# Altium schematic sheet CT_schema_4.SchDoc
size 282 x 169 mm
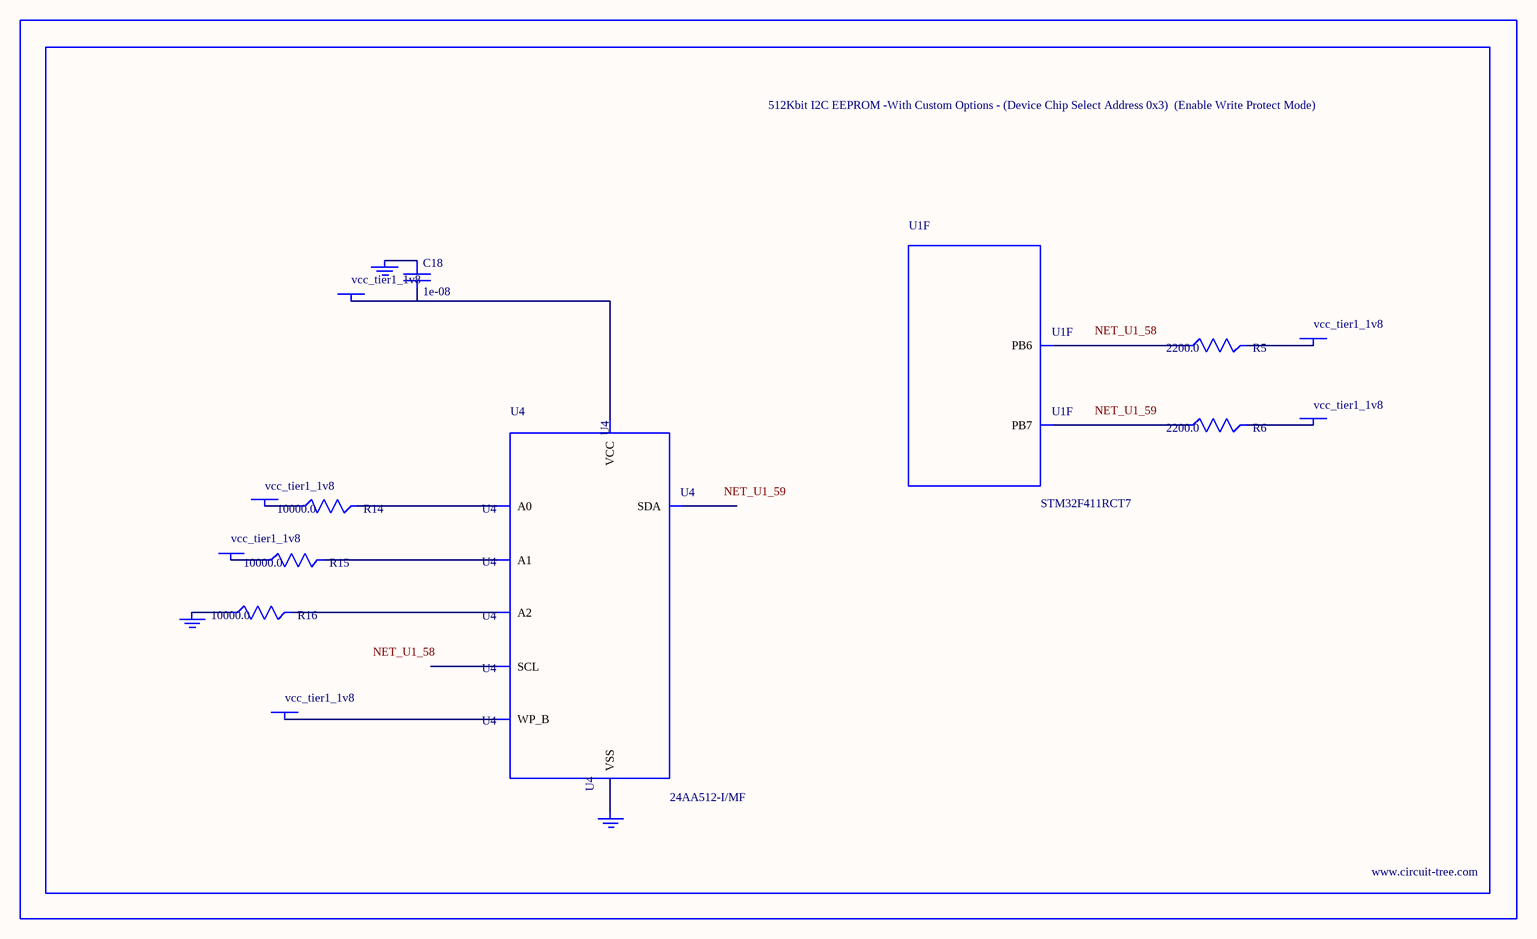
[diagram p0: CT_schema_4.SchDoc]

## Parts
BORDER3  (no value)
C18  1e-08  [C0402]
GND_INSTANCE_3_0  (no value)
GND_INSTANCE_3_1  (no value)
GND_INSTANCE_3_2  (no value)
POWER_INSTANCE_3_0  vcc_tier1_1v8
POWER_INSTANCE_3_1  vcc_tier1_1v8
POWER_INSTANCE_3_2  vcc_tier1_1v8
POWER_INSTANCE_3_3  vcc_tier1_1v8
POWER_INSTANCE_3_4  vcc_tier1_1v8
POWER_INSTANCE_3_5  vcc_tier1_1v8
R5  2200.0  [R0603]
R6  2200.0  [R0603]
R14  10000.0  [R0603]
R15  10000.0  [R0603]
R16  10000.0  [R0603]
U1  STM32F411RCT7  [LQFP64]  (part F of 8)
U4  24AA512-I/MF  [DFN8-S]

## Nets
NetC18_1: C18.1 GND_INSTANCE_3_1.0(GND)
NetC18_2: C18.2 POWER_INSTANCE_3_3.0(PWR) U4.8(VCC)
NetGND_INSTANCE_3_0_0: GND_INSTANCE_3_0.0(GND) R16.1
NetGND_INSTANCE_3_2_0: GND_INSTANCE_3_2.0(GND) U4.4(VSS)
NetPOWER_INSTANCE_3_0_0: POWER_INSTANCE_3_0.0(PWR) R14.1
NetPOWER_INSTANCE_3_1_0: POWER_INSTANCE_3_1.0(PWR) R15.1
NetPOWER_INSTANCE_3_2_0: POWER_INSTANCE_3_2.0(PWR) U4.7(WP_B)
NetPOWER_INSTANCE_3_4_0: POWER_INSTANCE_3_4.0(PWR) R5.2
NetPOWER_INSTANCE_3_5_0: POWER_INSTANCE_3_5.0(PWR) R6.2
NetR5_1: R5.1 U1.58(PB6)
NetR6_1: R6.1 U1.59(PB7)
NetR14_2: R14.2 U4.1(A0)
NetR15_2: R15.2 U4.2(A1)
NetR16_2: R16.2 U4.3(A2)

Not connected (* = marked no-connect by the designer): U4 5(SDA) 6(SCL)

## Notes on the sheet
- Labels drawn without touching a wire or pin: NET_U1_58, NET_U1_59

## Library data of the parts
BORDER3 = BORDER_PAGE3
C18 = C0402C103K3RAC
GND_INSTANCE_3_0-GND_INSTANCE_3_2 = GND
POWER_INSTANCE_3_0-POWER_INSTANCE_3_5 = PWR
R5 R6 = RC0603JR-072K2L
R14-R16 = RC0603JR-0710KL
